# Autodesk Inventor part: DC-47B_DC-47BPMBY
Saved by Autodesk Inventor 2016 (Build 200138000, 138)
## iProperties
Created: 2015-09
Part Number: DC-47B_DC-47BPMBY
Material: Generic
Document SubType Name: Modeling
Designer: irish_000
Density: 1 g/cm^3
Appearance: Default
Author: irish_000
Revision Number: ANY
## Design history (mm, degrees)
feature "Rib2"
feature "_INSERT_-_#4-40 Tapped Hole2_" [Rib]
feature "Mirror5" [Rib]
feature "Mirror6[1]" [Rib]
feature "Mirror6[2]" [Rib]
body "Solid1"
body "Solid2"
body "Solid3"
body "Solid4"
body "Solid5"
